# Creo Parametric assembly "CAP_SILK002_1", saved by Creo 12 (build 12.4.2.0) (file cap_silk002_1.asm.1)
Units: Custom; MM, KILOGRAM, SECS

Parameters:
  PTC_WM_ITERATION = "0"
  PTC_WM_VERSION = "-.0"
  PTC_WM_LIFECYCLE_STATE = "In Work"
  PTC_WM_LIFECYCLE = "MO_CADDocument"
  PTC_WM_CREATED_BY = "Maximilian Roepper (Z0017RMS: MO)"
  PTC_WM_CREATED_ON = "18-Sep-26 11:36:42 AM"
  PTC_WM_MODIFIED_BY = "Maximilian Roepper (Z0017RMS: MO)"
  PTC_WM_MODIFIED_ON = "18-Sep-26 11:36:46 AM"
  PDMLINKNUMBER = "PDM000071454943"
  PTC_WM_NAME = "cap_silk002_1.asm"
  PTC_WM_NUMBER = "PDM000071454943"

Other parameters: WEIGHT, WEIGHT_FACTOR, WEIGHT_ADD, MC_ERRORS, SUPPLIER, ISPOSITIONINGASSEMBLY

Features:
  1. coordinate system
  2. imported feature
  3. component "CAP_SILK_UP001_1"
  4. component "CAP_SILK_DWN001_1"

Other named items: DRW_VIEW_ORG, ROUGH-GROB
